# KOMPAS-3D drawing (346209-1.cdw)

Referenced files: 2Ведомость.cdw
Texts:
  КП.ОКМЧЕП.МЕ.12. -00.000 ВП
  Відомість проекту
  Доля Инна
  Текст на чертеже
  Размерные надписи
  Шероховатость
  Линия-выноска #1
  Линия-выноска #2
  Линия-выноска #3
  Отклонения формы и база
  Заголовок таблицы
  Ячейка таблицы
  Стрелка вида
  Обозначение изменения
  Фигурная скобка
  Номер узла
  Марка координационной оси
  VRCB
  Выносная надпись
  Обозначение узла
  Марка/позиционное обозначение с линией-выноской
  Марка/позиционное обозначение на линии
  Марка/позиционное обозначение без линии-выноски
  КП.ОКМЧЕП.МЕ.92. -00.000 ТЗ
  КП.ОКМЧЕП.МЕ.92. -00.000 ПЗ
  КП.ОКМЧЕП.МЕ.92. -01.000 СК
  КП.ОКМЧЕП.МЕ.92. -02.000 СК
  КП.ОКМЧЕП.МЕ.92. -02.000 СП
  Документація загальна
  Технічне завдання
  Розрахунково-поясню-
  вальна записка
  Документація по
  складальних одиницях
  Складальне креслення
  привода
  Специфікація редуктора
  Специфікація привода
  Шарівський Я. В.
  Відомість
  проекту
  ПолтНТУ2009
  КП.ДМ.МА.33. -00.000 ВП-
  Таран В. В.
  КП.ОКМЧЕП.МЕ.92. -01.000 СП
Dimensions and other numbers on the sheet: 7; 4; 1; 3; 2; 0; 5; 6; 8; 9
